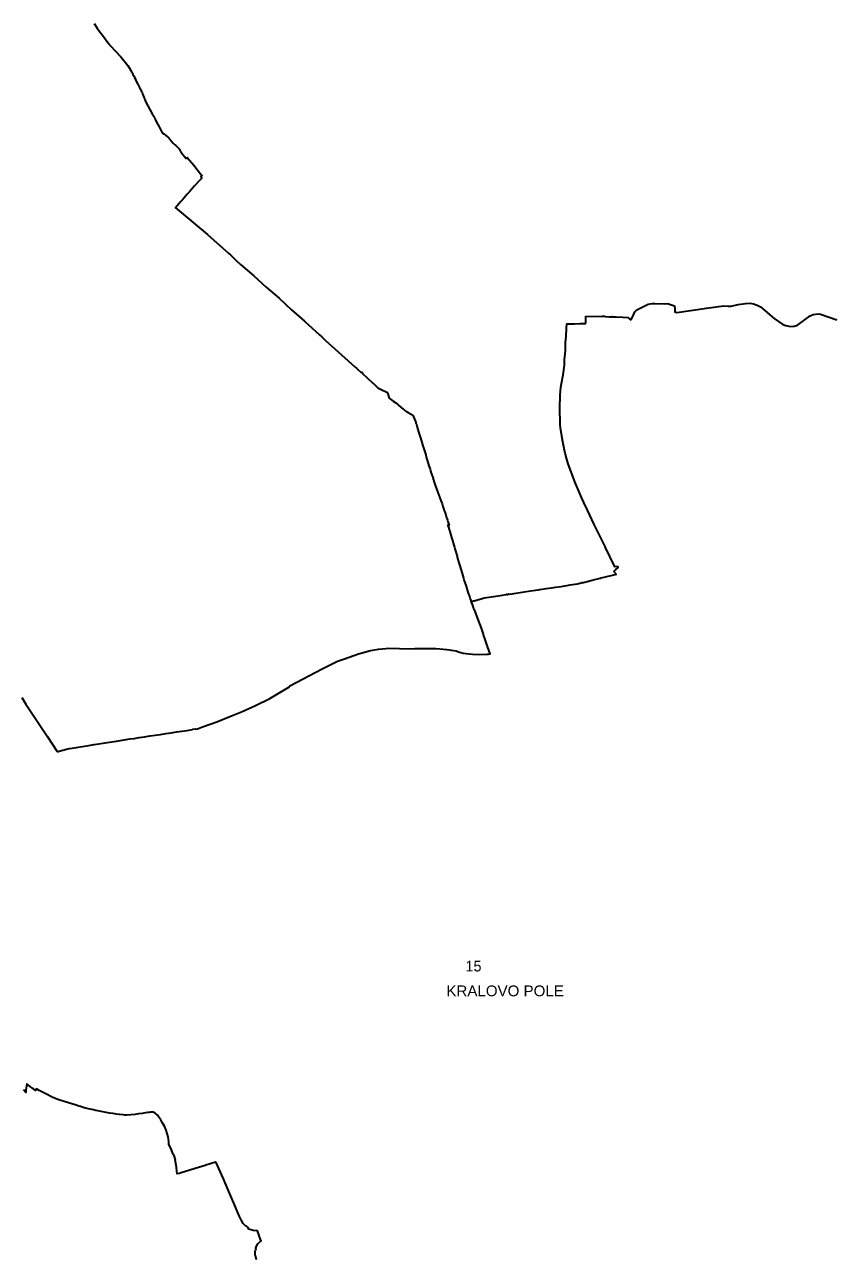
# Model space of a CAD drawing. Extents: x -610940 to -588976, y -1170376 to -1149800.
# Drawn here: x -600196 to -598311, y -1157770 to -1154902 of the extents above; entities that cross this region are included whole.
import ezdxf

# ---------------------------------------------------------------- set-up
doc = ezdxf.new("R2010")
doc.units = 0
doc.header["$LTSCALE"] = 10
doc.layers.add('54', color=7, linetype='Continuous', lineweight=35)
doc.layers.add('55', color=7, linetype='Continuous')
doc.layers.add('56', color=7, linetype='Continuous')

msp = doc.modelspace()

# ---------------------------------------------------------------- linework, layer by layer
at = {"layer": '54'}
for p, q in [((-598731.27, -1155551.24), (-598707.81, -1155551.64)), ((-598707.81, -1155551.64), (-598707.09, -1155551.7)), ((-598891.93, -1155580.24), (-598854.47, -1155581.36)), ((-598891.81, -1155597.43), (-598891.93, -1155580.24)), ((-598846.61, -1155581.6), (-598836.35, -1155581.94)), ((-598829.84, -1155582.16), (-598831.36, -1155582.09)), ((-598829.84, -1155582.16), (-598828.31, -1155582.23)), ((-598828.31, -1155582.23), (-598820.84, -1155582.47)), ((-598820.84, -1155582.47), (-598805.51, -1155582.97)), ((-598918.12, -1155598.08), (-598904.99, -1155597.75)), ((-598904.99, -1155597.75), (-598891.81, -1155597.43)), ((-598938.93, -1155660.84), (-598938.86, -1155641.8)), ((-598938.86, -1155641.8), (-598937.46, -1155628.08)), ((-598941.02, -1155681.74), (-598940.94, -1155680.77)), ((-598940.94, -1155680.77), (-598939.9, -1155668.93)), ((-598939.9, -1155668.93), (-598938.93, -1155660.84)), ((-598948.4, -1155737.3), (-598944.35, -1155717.09)), ((-598952.08, -1155794.82), (-598951.52, -1155764.38)), ((-598949.55, -1155846.12), (-598951.3, -1155833.81)), ((-598944.95, -1155873.33), (-598949.55, -1155846.12)), ((-598939.29, -1155899.88), (-598944.95, -1155873.33)), ((-598932.8, -1155923.82), (-598936.02, -1155913.63)), ((-598917.64, -1155963.5), (-598932.8, -1155923.82)), ((-598877.09, -1156194.98), (-598867.75, -1156192.66)), ((-598867.75, -1156192.66), (-598864.43, -1156191.85)), ((-598864.43, -1156191.85), (-598858.2, -1156190.29)), ((-598858.2, -1156190.29), (-598856.72, -1156189.96)), ((-598820.41, -1156181.89), (-598856.72, -1156189.96)), ((-598931.81, -1156206.46), (-598928.24, -1156205.92)), ((-598928.24, -1156205.92), (-598916.96, -1156204.11)), ((-598916.96, -1156204.11), (-598916.04, -1156203.88)), ((-599111.41, -1156233.58), (-599100.63, -1156231.86)), ((-599100.63, -1156231.86), (-599085.55, -1156229.59)), ((-599085.55, -1156229.59), (-599076.46, -1156228.42)), ((-599076.12, -1156228.37), (-599076.46, -1156228.42)), ((-599074.79, -1156228.17), (-599076.12, -1156228.37)), ((-599074.79, -1156228.17), (-599072.82, -1156227.87)), ((-599072.82, -1156227.87), (-599072.09, -1156227.74)), ((-599072.09, -1156227.74), (-599071.29, -1156227.64)), ((-599070.73, -1156227.56), (-599071.29, -1156227.64)), ((-600203.4, -1156467.99), (-600193.54, -1156482.97)), ((-600193.54, -1156482.97), (-600144.31, -1156557.79)), ((-599799.83, -1156541.45), (-599806.49, -1156542.41)), ((-599799.56, -1156541.41), (-599799.83, -1156541.45)), ((-600144.31, -1156557.79), (-600120.76, -1156593.54)), ((-600086.22, -1156585.49), (-600043.31, -1156578.37)), ((-600070.47, -1157418.3), (-600074.3, -1157417.14)), ((-600066.51, -1157419.55), (-600070.47, -1157418.3)), ((-600057.93, -1157422.06), (-600066.51, -1157419.55)), ((-600030.82, -1157428.49), (-600036.63, -1157427.19)), ((-599851.36, -1157530.07), (-599854.08, -1157522.55)), ((-599835.04, -1157574.74), (-599836.27, -1157575)), ((-599829.95, -1157573.13), (-599835.04, -1157574.74)), ((-599792.25, -1157561.19), (-599829.95, -1157573.13)), ((-599660.17, -1157765.25), (-599657.77, -1157775.24)), ((-599659.08, -1157750.32), (-599659.87, -1157754.51))]:
    msp.add_line(p, q, dxfattribs=at)
for points in [[(-600034.91, -1154899.9), (-600027.56, -1154910.4), (-600019.07, -1154922.44), (-600018.93, -1154922.63), (-600018.82, -1154922.79), (-600015.79, -1154927.09), (-600000.75, -1154947.41), (-599999.56, -1154948.66), (-599997.51, -1154950.95), (-599997.3, -1154951.17), (-599972.63, -1154977.55), (-599969.26, -1154981.71), (-599956.5, -1154997.5), (-599950.58, -1155007.86), (-599949.85, -1155009.11), (-599947.74, -1155012.73), (-599946.65, -1155014.58)], [(-599946.65, -1155014.58), (-599945.82, -1155016.01), (-599944.77, -1155018.08), (-599942.9, -1155021.79), (-599941.14, -1155025.3), (-599939.07, -1155029.4), (-599938.57, -1155030.39), (-599936.97, -1155034.1), (-599935.03, -1155037.68), (-599933.13, -1155041.42), (-599932.66, -1155042.27), (-599931.15, -1155045.34), (-599929.45, -1155048.71), (-599929.16, -1155049.1), (-599927.4, -1155052.73), (-599925.49, -1155056.24), (-599924.04, -1155059.08), (-599923.52, -1155060.39), (-599922.22, -1155063.57), (-599919.29, -1155070.82), (-599918.85, -1155071.9), (-599918.38, -1155073.08), (-599916.95, -1155076.59), (-599915.94, -1155079.13), (-599914.42, -1155082.82), (-599909.68, -1155091.08), (-599898.87, -1155111.46), (-599897.1, -1155114.86), (-599896.92, -1155114.78), (-599892.7, -1155122.61), (-599893.01, -1155122.75), (-599886.8, -1155134.69), (-599883.72, -1155140.47), (-599876.87, -1155154.03), (-599872.68, -1155156.72), (-599868.97, -1155159.69), (-599864.57, -1155163.22), (-599863.54, -1155164.05), (-599861.53, -1155165.43), (-599858.95, -1155168.68)], [(-599858.95, -1155168.68), (-599851.01, -1155178.37), (-599847.1, -1155181.66), (-599845.18, -1155183.63), (-599837.44, -1155191.58), (-599833.88, -1155197.6), (-599833.63, -1155197.92), (-599828.35, -1155204.67), (-599824.61, -1155209.44), (-599821.26, -1155213.71), (-599821.16, -1155213.85), (-599818.41, -1155211.6), (-599803.28, -1155229.62), (-599784.99, -1155252.4), (-599784.77, -1155252.67), (-599784.06, -1155253.52), (-599785.56, -1155255.09), (-599786.94, -1155256.63), (-599786.37, -1155257.33), (-599785.27, -1155258.66), (-599784.27, -1155259.55), (-599789.12, -1155264.31), (-599801.19, -1155277.66), (-599813.48, -1155291.42), (-599817.43, -1155295.8), (-599818.67, -1155297.16), (-599821.24, -1155300), (-599825.51, -1155304.93), (-599829.4, -1155309.66), (-599833.36, -1155314.2), (-599837.3, -1155318.58), (-599845.88, -1155328.19), (-599842.11, -1155331.34), (-599771.45, -1155390.67), (-599721.42, -1155434.66), (-599718.13, -1155437.76), (-599712.45, -1155443.13), (-599708.56, -1155447.2), (-599707.68, -1155448.03), (-599706.72, -1155448.94)], [(-599706.72, -1155448.94), (-599705.4, -1155450.18), (-599703.53, -1155451.94), (-599694.86, -1155460.11), (-599663.93, -1155486.78), (-599634.83, -1155513.16), (-599604.32, -1155539.1), (-599575.86, -1155565.74), (-599545.58, -1155592.34), (-599511.24, -1155623.82), (-599505.64, -1155628.94), (-599496.81, -1155637.05), (-599451.93, -1155677.63), (-599428.91, -1155698.12), (-599425.2, -1155701.43), (-599422.14, -1155703.7), (-599413.61, -1155711.57), (-599411.3, -1155711.12), (-599410.73, -1155714.24), (-599387.57, -1155735.63), (-599386.91, -1155736.25), (-599386.43, -1155736.69), (-599381.72, -1155741.14), (-599375.15, -1155747.26), (-599369.37, -1155750.2), (-599352.62, -1155758.55), (-599352.5, -1155758.61), (-599348.5, -1155770.99), (-599339.63, -1155778.12), (-599333.57, -1155781.85), (-599328.65, -1155785.99), (-599326.23, -1155788.24), (-599316.16, -1155796.68), (-599313.61, -1155798.86), (-599312.36, -1155799.91), (-599311.34, -1155800.8), (-599309.12, -1155802.69), (-599308.92, -1155802.78), (-599304.98, -1155804.89), (-599293.68, -1155810.94)], [(-598786.26, -1155589.12), (-598780.07, -1155576.19), (-598777.54, -1155570.64), (-598773.04, -1155566.06), (-598763.59, -1155561.04)], [(-598763.59, -1155561.04), (-598746.67, -1155552.31), (-598737.41, -1155551.33), (-598736.94, -1155551.36), (-598731.88, -1155551.29), (-598731.27, -1155551.24)], [(-598707.09, -1155551.7), (-598701.6, -1155551.31), (-598685.34, -1155556.25), (-598684.9, -1155563.65), (-598684.42, -1155570.71), (-598679.82, -1155571.81)], [(-598679.82, -1155571.81), (-598611.22, -1155562.02), (-598571.66, -1155556.66)], [(-598571.66, -1155556.66), (-598560.48, -1155557.26), (-598553.33, -1155557.13), (-598536.98, -1155553.52), (-598520.55, -1155550.82), (-598510.17, -1155550.59), (-598501.95, -1155551.99), (-598493.14, -1155554.9), (-598485.56, -1155559.21), (-598453.35, -1155585.87), (-598433.4, -1155599.76), (-598426.36, -1155602.39), (-598415.52, -1155604.3), (-598407.36, -1155603.89), (-598399.18, -1155601.4), (-598370.19, -1155579.95), (-598363.06, -1155576.66), (-598351.35, -1155575.39), (-598346.06, -1155575.76), (-598307.63, -1155589.43)], [(-598846.61, -1155581.6), (-598848.16, -1155581.55), (-598854.47, -1155581.36)], [(-598836.35, -1155581.94), (-598833.24, -1155582.05), (-598831.36, -1155582.09)], [(-598805.51, -1155582.97), (-598794, -1155583.63), (-598791.91, -1155584.91), (-598789.65, -1155586.43), (-598786.26, -1155589.12)], [(-598937.46, -1155628.08), (-598936.37, -1155608.26), (-598936.02, -1155598.51), (-598930.1, -1155598.42), (-598925.97, -1155598.35), (-598918.12, -1155598.08)], [(-598944.35, -1155717.09), (-598941.43, -1155694.45), (-598941.02, -1155681.74)], [(-598951.52, -1155764.38), (-598950.06, -1155746.04), (-598948.4, -1155737.3)], [(-598951.3, -1155833.81), (-598951.43, -1155829.66), (-598952.1, -1155795.69), (-598952.08, -1155794.82)], [(-599293.68, -1155810.94), (-599288.4, -1155824.24), (-599288.01, -1155824.11), (-599286.51, -1155829.11), (-599286.48, -1155829.23), (-599285.9, -1155831.05), (-599285.86, -1155831.22), (-599285.61, -1155831.98), (-599282.68, -1155842.03), (-599279.67, -1155851.81), (-599276.78, -1155861.15), (-599273.68, -1155871.62), (-599270.42, -1155882.19), (-599266.77, -1155894.09), (-599263.96, -1155903.42), (-599262.46, -1155908.48), (-599261.71, -1155910.88), (-599260.17, -1155915.51), (-599256.26, -1155928.5), (-599253.85, -1155936.37), (-599251.82, -1155943.36), (-599247.55, -1155956.27), (-599246.79, -1155958.56), (-599246.38, -1155959.78), (-599244.97, -1155964.05), (-599244.66, -1155965.07), (-599244.05, -1155966.83), (-599242.43, -1155971.7), (-599241.83, -1155973.53), (-599235.85, -1155991.12), (-599235.05, -1155993.48), (-599234.45, -1155994.79), (-599230.04, -1156005.86), (-599225.9, -1156017.2), (-599224.82, -1156020.13), (-599224.48, -1156021.07), (-599223.83, -1156023.08), (-599219.92, -1156035.14), (-599219.59, -1156036.17), (-599217.36, -1156043.04)], [(-598936.02, -1155913.63), (-598938.04, -1155905.23), (-598938.25, -1155904.27), (-598939.29, -1155899.88)], [(-598817.72, -1156163.2), (-598824.19, -1156163.45), (-598824.54, -1156162.37), (-598845.61, -1156119.15), (-598846.92, -1156116.4), (-598857.42, -1156094.7), (-598871.96, -1156065.22), (-598887.77, -1156032.15), (-598896.33, -1156014.17), (-598901.02, -1156004.38), (-598916.87, -1155965.64), (-598917.64, -1155963.5)], [(-599217.36, -1156043.04), (-599216.23, -1156046.51), (-599216.09, -1156046.94), (-599215.23, -1156049.59), (-599214.82, -1156050.84), (-599213.3, -1156055.52), (-599212.51, -1156057.97), (-599211.41, -1156060.8), (-599209.17, -1156066.6), (-599209.03, -1156067.01), (-599210.03, -1156066.9), (-599212.74, -1156066.6), (-599212.63, -1156067.12), (-599212.43, -1156067.71), (-599211.25, -1156071.24), (-599209.38, -1156076.82), (-599209.18, -1156077.46), (-599208.09, -1156080.97), (-599207.93, -1156081.52), (-599203.74, -1156095.75), (-599201.16, -1156104.53), (-599200.86, -1156105.51), (-599198.53, -1156113.32), (-599197.27, -1156117.73), (-599195.98, -1156122.09), (-599190.92, -1156139.19), (-599190.37, -1156141.04), (-599186.48, -1156154.17), (-599184.34, -1156161.43), (-599179.08, -1156179.21), (-599176.1, -1156189.83), (-599174.27, -1156196.15), (-599170.86, -1156206.75), (-599165.76, -1156222.58), (-599164.98, -1156224.94), (-599163.7, -1156228.85), (-599163.12, -1156230.4), (-599161.28, -1156235.36), (-599160.36, -1156237.86), (-599158.11, -1156243.94)], [(-598820.41, -1156181.89), (-598826.77, -1156175), (-598822.6, -1156171.09), (-598816.66, -1156165.34), (-598817.72, -1156163.2)], [(-598916.04, -1156203.88), (-598911.09, -1156203.12), (-598908.21, -1156202.66), (-598900.05, -1156200.6), (-598896.99, -1156199.86), (-598885.72, -1156197.12), (-598877.09, -1156194.98)], [(-599070.73, -1156227.56), (-599062.87, -1156226.29), (-599059.06, -1156225.65), (-599020.15, -1156219.86)], [(-599020.15, -1156219.86), (-599002.07, -1156217.1), (-598999.38, -1156216.69), (-598998.69, -1156216.6), (-598983.41, -1156214.28), (-598966.06, -1156211.71), (-598961.71, -1156211.11), (-598948.93, -1156209.25), (-598944.26, -1156208.55), (-598931.81, -1156206.46)], [(-599158.11, -1156243.94), (-599158.03, -1156244.17), (-599157.83, -1156244.7)], [(-599157.83, -1156244.7), (-599156.76, -1156244.32), (-599152.52, -1156243.02), (-599150.93, -1156242.5), (-599132.98, -1156237.33), (-599130.49, -1156236.58)], [(-599120.21, -1156348.74), (-599125.6, -1156332.64), (-599129.12, -1156322.15), (-599129.83, -1156320.33), (-599133.46, -1156309.08), (-599136.48, -1156300.07), (-599139.38, -1156292.27), (-599149.67, -1156265.27), (-599150.88, -1156264.22), (-599152.6, -1156258.09), (-599155.37, -1156251.14), (-599157.83, -1156244.7)], [(-599130.49, -1156236.58), (-599128.16, -1156235.95), (-599111.41, -1156233.58)], [(-599659.48, -1156486.04), (-599626.37, -1156470.03), (-599611.1, -1156461.01), (-599581.83, -1156443.74), (-599580.13, -1156440.87), (-599519.75, -1156408.95), (-599504.7, -1156401.27), (-599489.05, -1156393.39), (-599468.77, -1156383.55), (-599452.61, -1156377.76), (-599419.95, -1156366.31), (-599392.62, -1156358.47), (-599373.31, -1156355.45), (-599356.89, -1156353.63)], [(-599356.89, -1156353.63), (-599351.42, -1156353.15), (-599298.62, -1156354.18), (-599288.79, -1156354.06), (-599271.19, -1156353.8), (-599263.74, -1156353.6), (-599260.05, -1156353.45), (-599248.9, -1156353.8), (-599242.6, -1156354.02), (-599240.69, -1156354.04), (-599231.42, -1156354.63), (-599214.99, -1156355.77), (-599208.59, -1156356.91), (-599205.04, -1156357.44), (-599192.95, -1156359.49), (-599187.54, -1156361.29), (-599176.46, -1156364.75), (-599163.09, -1156366.31), (-599155.4, -1156366.87)], [(-599155.4, -1156366.87), (-599140.79, -1156367.97), (-599121.72, -1156366.78)], [(-599121.72, -1156366.78), (-599117.84, -1156366.58), (-599114.36, -1156366.32), (-599120.21, -1156348.74)], [(-599749.53, -1156524.36), (-599719, -1156511.85), (-599692.58, -1156500.93), (-599659.48, -1156486.04)], [(-599880.31, -1156553.52), (-599868.08, -1156551.73), (-599855.7, -1156549.93), (-599843.44, -1156548.02), (-599831.23, -1156546.21), (-599818.74, -1156544.33), (-599806.49, -1156542.41)], [(-599799.56, -1156541.41), (-599794.61, -1156540.51), (-599782.59, -1156536.38), (-599749.53, -1156524.36)], [(-600043.31, -1156578.37), (-600035.91, -1156577.14), (-600033.85, -1156576.83), (-600009.31, -1156573.1), (-600004.88, -1156572.46), (-599983.12, -1156569.08), (-599951.69, -1156564.23), (-599942.15, -1156562.77), (-599929.87, -1156560.96), (-599917.43, -1156559.08), (-599905.21, -1156557.21), (-599904.65, -1156557.16)], [(-599904.65, -1156557.16), (-599892.66, -1156555.42), (-599880.31, -1156553.52)], [(-600120.76, -1156593.54), (-600118.83, -1156593.03), (-600113.74, -1156591.8)], [(-600113.74, -1156591.8), (-600092.75, -1156586.58), (-600086.22, -1156585.49)], [(-600182.59, -1157373.76), (-600191.53, -1157366.84), (-600193.46, -1157381.58), (-600193.92, -1157386.42), (-600199.32, -1157380.52)], [(-600176.24, -1157378.54), (-600177.1, -1157377.72), (-600182.59, -1157373.76)], [(-600074.3, -1157417.14), (-600081.62, -1157414.94), (-600084.8, -1157414.03), (-600096.73, -1157410.38), (-600104.5, -1157407.83), (-600114.58, -1157404.56), (-600119.52, -1157402.91), (-600132.28, -1157397.26), (-600147.56, -1157389.74), (-600162.4, -1157381.85), (-600169.09, -1157378.17), (-600171.42, -1157382.1), (-600176.24, -1157378.54)], [(-600036.63, -1157427.19), (-600051.51, -1157423.72), (-600057.68, -1157422.14), (-600057.93, -1157422.06)], [(-599901.88, -1157432.46), (-599903.77, -1157432.37), (-599907.12, -1157432.98), (-599910.99, -1157433.51), (-599915.29, -1157434.2), (-599923.48, -1157435.55), (-599931.53, -1157436.58), (-599939.63, -1157437.54), (-599949.86, -1157438.83), (-599959.81, -1157439.26), (-599963.77, -1157439.26), (-599967.54, -1157438.9), (-599975.56, -1157437.89), (-599983.35, -1157436.87), (-599986.88, -1157436.33), (-599991.13, -1157435.7), (-599998.88, -1157434.49), (-600006.64, -1157433.19), (-600014.58, -1157431.66), (-600022.29, -1157430.1), (-600030.03, -1157428.56), (-600030.82, -1157428.49)], [(-599854.08, -1157522.55), (-599855.75, -1157518.06), (-599860.89, -1157507.72), (-599861.14, -1157501.82), (-599861.62, -1157495.31), (-599863.05, -1157489.67), (-599867.17, -1157474.01), (-599870.97, -1157465.07), (-599876.41, -1157456.43), (-599880.17, -1157450.23), (-599884.27, -1157443.98), (-599887.9, -1157439.45), (-599892.96, -1157435), (-599897.78, -1157432.78), (-599901.88, -1157432.46)], [(-599851.36, -1157530.07), (-599848.92, -1157535.88), (-599846.77, -1157543.29)], [(-599836.27, -1157575), (-599841.51, -1157576.2), (-599842.24, -1157569.81), (-599843.65, -1157560.79), (-599846.77, -1157543.29)], [(-599751.63, -1157548.31), (-599753, -1157548.72), (-599762.57, -1157551.87), (-599765.23, -1157552.63), (-599775.54, -1157555.91), (-599776.58, -1157556.25), (-599792.25, -1157561.19)], [(-599659.08, -1157750.32), (-599658.58, -1157748.78), (-599657.09, -1157744.17), (-599653.98, -1157738.42), (-599647.6, -1157732.13), (-599646.75, -1157731.6), (-599648.66, -1157726.28), (-599650.89, -1157720.11), (-599651.13, -1157719.44), (-599655.05, -1157708.55), (-599665.12, -1157707.56), (-599674.93, -1157704.33), (-599677.58, -1157700.94), (-599680.55, -1157697.72), (-599681.85, -1157697.33), (-599683.02, -1157697.22), (-599688.35, -1157691.38), (-599692.54, -1157684.59), (-599697.25, -1157675.04), (-599729.86, -1157597.17), (-599734.16, -1157587.44), (-599751.63, -1157548.31)], [(-599660.17, -1157765.25), (-599660.12, -1157755.86), (-599659.87, -1157754.51)]]:
    msp.add_lwpolyline(points, dxfattribs=at)

# ---------------------------------------------------------------- texts
at = {"layer": '55', "width": 1.05}
msp.add_text('KRALOVO POLE', height=25, dxfattribs=at).set_placement((-599215.81, -1157162.76))
at = {"layer": '56'}
msp.add_text('15 ', height=25, dxfattribs=at).set_placement((-599171.31, -1157105.17))

doc.saveas('drawing.dxf')
